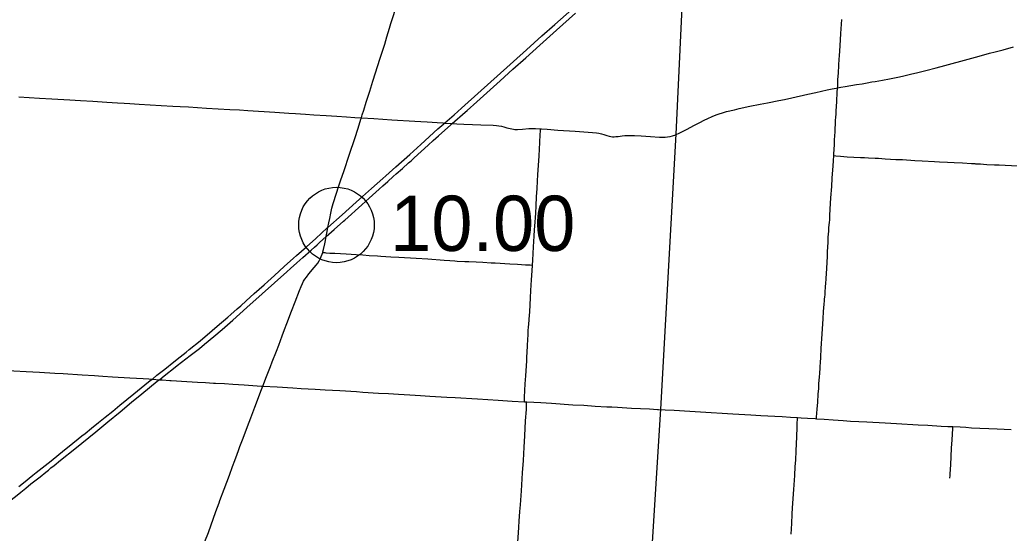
# Model space of a CAD drawing. Extents: x 1813937 to 1948437, y 826606 to 1022856.
# Drawn here: x 1890191 to 1909861, y 893308 to 903518 of the extents above; entities that cross this region are included whole.
import ezdxf

# ---------------------------------------------------------------- set-up
doc = ezdxf.new("R2010")
doc.units = 0
for name, color, linetype in [('Default', 7, 'Continuous'), ('GM_X_County_Road', 7, 'Continuous'), ('GM_X_Interstate_Route', 7, 'Continuous'), ('GM_X_Township', 7, 'Continuous'), ('GM_X_Township_Road', 7, 'Continuous')]:
    doc.layers.add(name, color=color, linetype=linetype)

msp = doc.modelspace()

# ---------------------------------------------------------------- linework, layer by layer
at = {"layer": 'Default'}
msp.add_circle((1896487, 899438), 750, dxfattribs=at)
at = {"layer": 'GM_X_County_Road'}
for points in [[(1896982, 901567), (1896992, 901599), (1897000, 901626), (1897029, 901721), (1897078, 901878), (1897148, 902097), (1897213, 902300), (1897356, 902754), (1897446, 903035), (1897489, 903176), (1897540, 903349), (1897570, 903443), (1897615, 903583), (1897689, 903818), (1897736, 903976), (1897784, 904133), (1897819, 904246)], [(1906450, 902166), (1906451, 902181), (1906457, 902331), (1906466, 902459), (1906475, 902615), (1906483, 902732), (1906488, 902803), (1906501, 902999), (1906515, 903244), (1906534, 903523)], [(1906450, 902166), (1906516, 902180), (1906597, 902193), (1906710, 902211), (1906824, 902228), (1906937, 902246), (1907034, 902263), (1907131, 902281), (1907195, 902292), (1907339, 902317), (1907484, 902343), (1907645, 902374), (1907740, 902395), (1907899, 902434), (1908043, 902469), (1908202, 902508), (1908408, 902564), (1908582, 902612), (1908724, 902650), (1908899, 902696), (1909121, 902755), (1909263, 902794), (1909468, 902851), (1909579, 902880), (1909738, 902923), (1909944, 902978)], [(1903187, 901216), (1903212, 901224), (1903242, 901236), (1903301, 901263), (1903447, 901339), (1903607, 901423), (1903708, 901476), (1903795, 901522), (1903869, 901557), (1903959, 901597), (1904035, 901627), (1904097, 901650), (1904160, 901670), (1904239, 901691), (1904399, 901729), (1904495, 901752), (1904703, 901798), (1904912, 901841), (1905057, 901869), (1905282, 901912), (1905395, 901935), (1905539, 901965), (1905859, 902036), (1906019, 902073), (1906243, 902123), (1906339, 902144), (1906420, 902160), (1906450, 902166)], [(1906373, 900816), (1906375, 900843), (1906387, 901039), (1906391, 901121), (1906397, 901219), (1906400, 901285), (1906410, 901514), (1906414, 901579), (1906418, 901644), (1906421, 901692), (1906428, 901805), (1906433, 901882), (1906435, 901931), (1906436, 901968), (1906438, 902008), (1906442, 902067), (1906450, 902166)], [(1890172, 901983), (1890581, 901959), (1890827, 901943), (1891187, 901926), (1891400, 901916), (1891646, 901901), (1891924, 901882), (1892137, 901869), (1892268, 901859), (1892382, 901852), (1892562, 901841), (1893004, 901815), (1893234, 901803), (1893381, 901796), (1893545, 901785), (1893905, 901763), (1894134, 901750), (1894364, 901736), (1894560, 901725), (1894724, 901716), (1895264, 901683), (1895543, 901663), (1895674, 901655), (1895870, 901642), (1896034, 901631), (1896279, 901615), (1896492, 901601), (1896688, 901587), (1896852, 901576), (1896982, 901567)], [(1896353, 899565), (1896375, 899674), (1896398, 899770), (1896424, 899865), (1896488, 900068), (1896528, 900193), (1896575, 900334), (1896634, 900504), (1896749, 900846), (1896851, 901158), (1896917, 901361), (1896974, 901542), (1896982, 901567)], [(1896982, 901567), (1897228, 901552), (1897588, 901530), (1898047, 901502), (1898162, 901494), (1898292, 901486), (1898489, 901474), (1898600, 901466)], [(1898600, 901466), (1898620, 901464), (1898635, 901463), (1898751, 901456), (1898789, 901454), (1898882, 901449), (1899022, 901442)], [(1899022, 901442), (1899192, 901433), (1899356, 901427), (1899602, 901420), (1899668, 901415), (1899717, 901409), (1899765, 901400), (1899813, 901389), (1899877, 901372), (1899940, 901354), (1899972, 901347), (1900004, 901342), (1900036, 901339), (1900085, 901339), (1900183, 901345), (1900314, 901355), (1900379, 901356), (1900445, 901356), (1900544, 901351)], [(1900544, 901351), (1900560, 901351), (1900675, 901343), (1900887, 901326), (1901231, 901302), (1901574, 901277), (1901656, 901269), (1901705, 901261), (1901753, 901250), (1901801, 901236), (1901863, 901216), (1901910, 901203), (1901942, 901197), (1901974, 901193), (1902007, 901192), (1902039, 901194), (1902088, 901200), (1902169, 901211), (1902218, 901215), (1902284, 901217), (1902415, 901215), (1902547, 901210), (1902727, 901199), (1902907, 901185), (1902972, 901182), (1903021, 901184), (1903069, 901190), (1903118, 901198), (1903165, 901209), (1903187, 901216)], [(1906028, 895584), (1906031, 895616), (1906038, 895695), (1906046, 895777), (1906056, 895911), (1906066, 896074), (1906073, 896189), (1906078, 896287), (1906083, 896342), (1906089, 896421), (1906095, 896485), (1906103, 896600), (1906104, 896609), (1906105, 896628), (1906110, 896699), (1906115, 896809), (1906124, 896981), (1906142, 897276), (1906162, 897570), (1906172, 897718), (1906182, 897862), (1906188, 897926), (1906192, 897979), (1906194, 897996), (1906199, 898060), (1906205, 898140), (1906207, 898171), (1906209, 898198), (1906212, 898239), (1906214, 898255), (1906215, 898287), (1906219, 898351), (1906223, 898383), (1906229, 898465), (1906236, 898579), (1906247, 898809), (1906248, 898838), (1906251, 898902), (1906257, 899003), (1906260, 899089), (1906264, 899192), (1906272, 899313), (1906277, 899379), (1906283, 899440), (1906288, 899487), (1906292, 899542), (1906296, 899628), (1906302, 899750), (1906309, 899863), (1906317, 899977), (1906332, 900206), (1906342, 900370), (1906358, 900615), (1906365, 900712), (1906373, 900816)], [(1896262, 899099), (1896283, 899206), (1896295, 899272), (1896318, 899390), (1896336, 899481), (1896353, 899565)], [(1896215, 898893), (1896218, 898903), (1896231, 898950), (1896254, 899063), (1896262, 899099)], [(1895023, 896233), (1895096, 896422), (1895174, 896621), (1895209, 896713), (1895292, 896927), (1895339, 897049), (1895374, 897141), (1895409, 897233), (1895456, 897356), (1895502, 897478), (1895596, 897724), (1895666, 897907), (1895754, 898138), (1895784, 898214), (1895811, 898274), (1895834, 898317), (1895860, 898359), (1895888, 898399), (1895940, 898463), (1896045, 898590), (1896085, 898641), (1896114, 898681), (1896140, 898722), (1896164, 898765), (1896185, 898810), (1896203, 898856), (1896215, 898893)], [(1889661, 896565), (1890072, 896540), (1890318, 896526), (1890580, 896510), (1890891, 896490), (1891055, 896481), (1891431, 896457), (1891677, 896442), (1891759, 896438)], [(1891759, 896438), (1891841, 896434), (1892037, 896421), (1892380, 896399), (1892642, 896383), (1892756, 896376)], [(1892756, 896376), (1892821, 896371), (1892839, 896370), (1892965, 896361), (1893019, 896357), (1893172, 896348)], [(1893172, 896348), (1893199, 896347), (1893510, 896326), (1893722, 896312), (1893886, 896303), (1894042, 896294)], [(1894042, 896294), (1894082, 896291), (1894263, 896282), (1894426, 896271), (1894655, 896257), (1894999, 896235), (1895023, 896233)], [(1895023, 896233), (1895310, 896218), (1895622, 896199), (1895785, 896189), (1896064, 896172), (1896260, 896160), (1896555, 896144), (1896882, 896124), (1897013, 896115), (1897324, 896096), (1897521, 896085), (1897717, 896071), (1897947, 896058), (1898160, 896046), (1898340, 896036), (1898454, 896029), (1898683, 896015), (1898847, 896004), (1899289, 895979), (1899699, 895953), (1899977, 895937), (1900222, 895922)], [(1900094, 893136), (1900106, 893316), (1900114, 893431), (1900122, 893545), (1900134, 893741), (1900143, 893872), (1900163, 894150), (1900186, 894511), (1900202, 894756), (1900218, 895018), (1900231, 895247), (1900248, 895542), (1900262, 895771), (1900267, 895886), (1900268, 895920)], [(1900222, 895922), (1900268, 895920)], [(1900268, 895920), (1900272, 895920), (1900550, 895905), (1900763, 895891), (1901189, 895864), (1901402, 895852), (1901631, 895837), (1901860, 895823), (1901958, 895818), (1902073, 895812), (1902351, 895798), (1902711, 895780), (1902867, 895771)], [(1902867, 895771), (1902891, 895770), (1903022, 895763), (1903202, 895753), (1903513, 895732), (1903726, 895720), (1903939, 895707), (1904152, 895695), (1904365, 895684), (1904725, 895663), (1904823, 895658), (1904922, 895652), (1905200, 895635), (1905347, 895626), (1905511, 895616), (1905654, 895608)], [(1905526, 893292), (1905538, 893504), (1905546, 893684), (1905555, 893815), (1905580, 894175), (1905586, 894273), (1905596, 894453), (1905609, 894633), (1905617, 894764), (1905626, 894944), (1905637, 895223), (1905645, 895419), (1905648, 895485), (1905653, 895588), (1905654, 895608)], [(1905654, 895608), (1905724, 895604), (1905854, 895596), (1906002, 895586), (1906028, 895584)], [(1906028, 895584), (1906182, 895575), (1906362, 895562), (1906558, 895548), (1906705, 895538), (1906869, 895530), (1907033, 895520), (1907393, 895500), (1907622, 895487), (1908048, 895465), (1908245, 895455), (1908507, 895439), (1908638, 895432), (1908736, 895428), (1908740, 895428)], [(1908740, 895428), (1908883, 895421), (1908998, 895414), (1909113, 895407), (1909276, 895399), (1909457, 895391), (1909620, 895383), (1909899, 895368)]]:
    msp.add_lwpolyline(points, dxfattribs=at)
at = {"layer": 'GM_X_Interstate_Route'}
for points in [[(1890173, 894236), (1890301, 894339), (1890377, 894400), (1890454, 894462), (1890518, 894513), (1890813, 894749), (1891082, 894964), (1891171, 895037), (1891426, 895243), (1891490, 895294), (1891618, 895397), (1891759, 895510), (1891886, 895613), (1892039, 895737), (1892178, 895852), (1892458, 896079), (1892752, 896317), (1892776, 896336), (1892821, 896371), (1892833, 896381), (1892919, 896449), (1893073, 896571), (1893252, 896716), (1893381, 896816), (1893496, 896910), (1893560, 896961), (1893776, 897137), (1894014, 897338), (1894114, 897423), (1894203, 897496), (1894240, 897529), (1894326, 897604), (1894387, 897659), (1894510, 897768), (1894584, 897832), (1894694, 897931), (1894851, 898075), (1895048, 898250), (1895121, 898316), (1895255, 898436), (1895449, 898613), (1895634, 898775), (1895695, 898830), (1895891, 899004), (1896074, 899169), (1896305, 899378), (1896318, 899390), (1896599, 899641), (1896881, 899891), (1897003, 900001), (1897186, 900165), (1897407, 900362), (1897468, 900416), (1897664, 900591), (1897946, 900841), (1898166, 901038), (1898505, 901348), (1898623, 901452), (1898635, 901463), (1898640, 901468), (1898824, 901631), (1898971, 901763), (1899362, 902113), (1899680, 902397), (1900267, 902922), (1900572, 903196), (1900828, 903427), (1901390, 903931)], [(1899085, 901717), (1899276, 901888), (1899740, 902304), (1899996, 902534), (1900253, 902764), (1900533, 903016), (1900863, 903312), (1901242, 903651)], [(1898410, 901117), (1898516, 901212), (1898761, 901430), (1898781, 901447), (1898789, 901454), (1899043, 901680), (1899085, 901717)], [(1896651, 899535), (1896992, 899840), (1897138, 899972), (1897333, 900148), (1897406, 900214), (1897505, 900300), (1897615, 900399), (1897676, 900453), (1897798, 900563), (1897921, 900672), (1897970, 900716), (1898030, 900771), (1898308, 901025), (1898410, 901117)], [(1895982, 898936), (1896051, 898998), (1896100, 899041), (1896149, 899086), (1896283, 899206), (1896442, 899348), (1896625, 899512), (1896651, 899535)], [(1893319, 896640), (1893579, 896842), (1893761, 896983), (1893863, 897065), (1894052, 897223), (1894214, 897362), (1894424, 897545), (1894705, 897796), (1895010, 898071), (1895255, 898289), (1895500, 898508), (1895573, 898573), (1895696, 898682), (1895819, 898790), (1895982, 898936)], [(1892617, 896081), (1892767, 896204), (1892925, 896329), (1892965, 896361), (1892974, 896368), (1893062, 896438), (1893281, 896611), (1893319, 896640)], [(1889825, 893815), (1889826, 893815), (1889916, 893887), (1890005, 893959), (1890056, 894000), (1890107, 894041), (1890209, 894124), (1890311, 894206), (1890414, 894288), (1890491, 894349), (1890594, 894431), (1890709, 894523), (1890760, 894564), (1890811, 894605), (1890875, 894657), (1891002, 894760), (1891283, 894987), (1891704, 895327), (1891944, 895526), (1892184, 895725), (1892412, 895913), (1892617, 896081)]]:
    msp.add_lwpolyline(points, dxfattribs=at)
at = {"layer": 'GM_X_Township'}
msp.add_lwpolyline([(1929313, 880637), (1926519, 880798), (1923978, 880945), (1923826, 880954), (1918127, 881283), (1915079, 881414), (1912418, 881561), (1907482, 881867), (1902065, 882212), (1902276, 885593), (1902366, 887154), (1902378, 887248), (1902624, 890798), (1902935, 895772), (1903241, 901246), (1903453, 905734), (1903500, 906547), (1903661, 909327)], dxfattribs=at)
at = {"layer": 'GM_X_Township_Road'}
for points in [[(1900383, 898640), (1900389, 898738), (1900403, 899000), (1900414, 899213), (1900423, 899344), (1900434, 899491), (1900441, 899589), (1900447, 899670), (1900455, 899817), (1900463, 899997), (1900474, 900161), (1900483, 900308), (1900491, 900439), (1900502, 900619), (1900514, 900815), (1900530, 901077), (1900539, 901240), (1900541, 901306), (1900544, 901351)], [(1906373, 900816), (1906411, 900812), (1906509, 900804), (1906640, 900796), (1906771, 900789), (1906902, 900782), (1906984, 900778), (1907066, 900773), (1907196, 900766), (1907262, 900763), (1907393, 900756), (1907606, 900743), (1907737, 900737), (1907982, 900722), (1908130, 900715), (1908375, 900702), (1908474, 900696), (1908637, 900688), (1908768, 900680), (1908932, 900671), (1909112, 900661), (1909127, 900660), (1909176, 900657), (1909193, 900656), (1909209, 900655), (1909273, 900652), (1909288, 900651), (1909353, 900647), (1909418, 900643), (1909566, 900637), (1909664, 900631), (1910025, 900611)], [(1896215, 898893), (1896258, 898889), (1896274, 898887), (1896356, 898880), (1896454, 898874), (1896683, 898862), (1896879, 898850), (1897010, 898841), (1897140, 898832), (1897304, 898822), (1897369, 898819), (1897467, 898813), (1897565, 898807), (1897729, 898798), (1898072, 898777), (1898301, 898763), (1898628, 898740), (1898742, 898731), (1898840, 898723), (1898889, 898720), (1899036, 898714), (1899118, 898711), (1899266, 898704), (1899396, 898696), (1899560, 898686), (1899642, 898682), (1899936, 898665), (1900083, 898656), (1900247, 898646), (1900340, 898642), (1900383, 898640)], [(1900222, 895922), (1900223, 895950), (1900225, 896015), (1900240, 896277), (1900250, 896440), (1900256, 896538), (1900263, 896637), (1900269, 896734), (1900273, 896800), (1900280, 896914), (1900286, 897028), (1900293, 897176), (1900297, 897241), (1900301, 897323), (1900305, 897421), (1900308, 897452), (1900311, 897487), (1900315, 897531), (1900317, 897563), (1900328, 897709), (1900342, 897987), (1900351, 898134), (1900364, 898346), (1900376, 898526), (1900383, 898640)], [(1894156, 893915), (1894171, 893957), (1894257, 894187), (1894307, 894326), (1894358, 894464), (1894421, 894633), (1894467, 894756), (1894512, 894879), (1894540, 894956), (1894569, 895033), (1894635, 895201), (1894720, 895431), (1894784, 895600), (1894863, 895816), (1894997, 896168), (1895009, 896199), (1895023, 896233)], [(1908678, 894405), (1908686, 894454), (1908690, 894487), (1908700, 894668), (1908716, 894998), (1908725, 895162), (1908738, 895393), (1908740, 895428)], [(1893871, 893141), (1893940, 893325), (1894092, 893741), (1894156, 893915)]]:
    msp.add_lwpolyline(points, dxfattribs=at)

# ---------------------------------------------------------------- texts
at = {"layer": 'Default'}
msp.add_text('10.00', height=1100, dxfattribs=at).set_placement((1897554, 898921))

doc.saveas('drawing.dxf')
